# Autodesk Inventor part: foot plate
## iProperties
Shininess: 64.0
Length Units: 11269
Angle Units: 11279
Time Units: 11290
Mass Units: 11283
Length Display Precision: 3
Angle Display Precision: 2
Compacted: True
Part Number: foot plate
Document SubType Name: Sheet Metal
Created: 2002-11
Designer: Elise Moss
Density: 0.0
Volumn: 0.0
Area: 0.0
PropertySet Name: Model Information
Control State: 0
Master: False
Checked Out: False
Author: Elise Moss
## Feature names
1. Corner Round1
2. Hole2
3. Plate1
4. Plate2
5. Bend1
6. Plate3
7. Bend2
